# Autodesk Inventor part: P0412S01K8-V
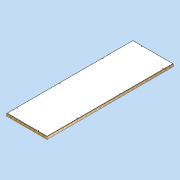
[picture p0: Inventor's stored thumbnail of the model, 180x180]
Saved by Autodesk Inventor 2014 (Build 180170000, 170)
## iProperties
Created: 2011-04
Part Number: P0412S01K8-V
Document SubType Name: Modeling
Designer: david.appleford
Density: 0.181878 g/cm^3
Description: 1w x 3w 01 Panel - 8 Locks
Cost Center: £180.00
Mass: 60000 g
Surface Area: 90367.8 cm^2
Volume: 329892 cm^3
Material: Generic
Appearance: Wood (Pine)
Justset: False
Title: 1w x 3w 01 Panel - 8 Locks
Author: david.appleford
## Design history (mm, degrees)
sketch "Sketch1"
  geometry: L1 (0, 0)-(1220, 0); L2 (1220, 0)-(1220, 3660); L3 (1220, 3660)-(0, 3660); L4 (0, 3660)-(0, 0); L5 (34, 3626)-(1186, 3626); L6 (1186, 3626)-(1186, 34); L7 (1186, 34)-(34, 34); L8 (34, 34)-(34, 3626)
  constraints: 16 end point, 4 parallel, 2 perpendicular, 1 horizontal, 3 other
  dimensions: "d0" = 1220 distance between parallel lines of L2 L4 (= w); "d1" = 3660 distance between parallel lines of L1 L3 (= 3 x w); "d2" = 34 distance between parallel lines of L5 L3 (= 0.5 x t)
extrude "Extrusion1" new body sketch "Sketch1" distance "d3" = 68 (= t); taper "d4" = 0 deg
sketch "Sketch2"
  geometry: L1 (1186, 3626)-(1186, 34) reference; L2 (34, 3626)-(1186, 3626) reference; L3 (34, 34)-(34, 3626) reference; L4 (1186, 34)-(34, 34) reference; L5 (1176, 3616)-(1176, 44); L6 (1176, 44)-(44, 44); L7 (44, 44)-(44, 3616); L8 (44, 3616)-(1176, 3616); 1 further point
  constraints: 8 end point, 3 other
  dimensions: "d5" = 10 distance between parallel lines of L8 L2
extrude "Extrusion2" join sketch "Sketch2" distance "d6" = 6 (= sw); taper "d7" = 0 deg
sketch "Sketch3"
  geometry: L1 (-44, 3616)-(-1176, 3616) reference; L2 (-1176, 3616)-(-1176, 44) reference; L3 (-44, 44)-(-44, 3616) reference; L4 (-1176, 44)-(-44, 44) reference; 1 further point
extrude "Extrusion3" join sketch "Sketch3" distance "d8" = 6 (= sw); taper "d9" = 0 deg
sketch "Sketch4"
  geometry: L1 (34, 3626)-(1186, 3626) reference; L2 (1186, 3626)-(1186, 34) reference; L3 (1186, 34)-(34, 34) reference; L4 (34, 34)-(34, 3626) reference; 9 further points
  constraints: 4 vertical alignment
  dimensions: "d10" = 28 distance from line of point (305, 3598) L1 (= k); "d11" = 28 distance from line of L2 point (1158, 3355) (= k); "d12" = 28 distance from line of L3 point (915, 62) (= k); "d13" = 28 distance from line of point (62, 305) L4 (= k); "d14" = 305 horizontal distance of point (305, 3598) point (0, 0) (= 0.25 x w); "d15" = 610 horizontal distance of point (915, 62) point (305, 3598) (= 0.5 x w); "d16" = 305 vertical distance of point (62, 305) point (0, 0) (= 0.25 x w); "d17" = 1220 distance of point (62, 305) point (62, 1525) (= w); "d18" = 1220 distance of point (62, 2745) point (62, 1525) (= w); "d19" = 610 vertical distance of point (1158, 915) point (62, 305) (= 0.5 x w); "d20" = 1220 distance of point (1158, 915) point (1158, 2135) (= w); "d21" = 1220 distance of point (1158, 3355) point (1158, 2135) (= w)
hole "Hole1" sketch "Sketch4" at (305, 3598), (62, 2745), (62, 1525), (62, 305), (1158, 3355), (1158, 2135), (1158, 915), (915, 62) diameter "d22" = 16.3; stored, may be unused: countersink angle "d26" = 90 deg, drill point angle "d28" = 118 deg; dims "d23" = 6, "d24" = 4, "d25" = 2, "d27" = 6
body "Solid1"
node "Projected Loop1"
other parameters: "w" = 1220 [user parameter; used in 10 equation terms], "t" = 68 [user parameter; used in 2 equation terms], "e" = 16 [user parameter], "sw" = 6 [user parameter; used in 2 equation terms], "sc" = 9 [user parameter], "sf" = 12 [user parameter], "k" = 28 [user parameter; used in 4 equation terms], "hd" = 12 [user parameter]
